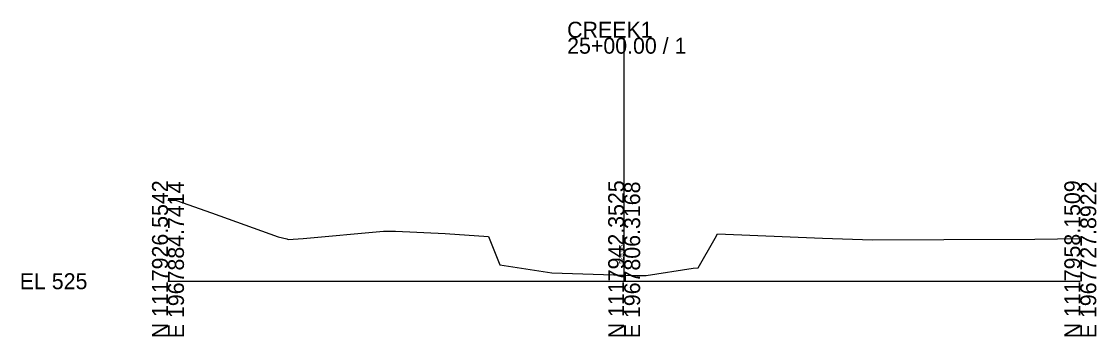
# Model space of a CAD drawing. Extents: x -26 to 163, y -10 to 10052.
# Drawn here: x -25.7 to 162.8, y 4490.3 to 4545.5 of the extents above; entities that cross this region are included whole.
import ezdxf

# ---------------------------------------------------------------- set-up
doc = ezdxf.new("R2010")
doc.units = 0
for name, color, linetype in [('RD_GPK_XS_Cell', 7, 'Continuous'), ('RD_XS_ExGround', 7, 'Continuous'), ('RD_XS_TX_Elev_EX', 7, 'Continuous')]:
    doc.layers.add(name, color=color, linetype=linetype)

msp = doc.modelspace()

# ---------------------------------------------------------------- linework, layer by layer
at = {"layer": 'RD_GPK_XS_Cell'}
for p, q in [((80, 4500), (80, 4542.7)), ((0, 4500), (80, 4500)), ((80, 4500), (160, 4500))]:
    msp.add_line(p, q, dxfattribs=at)
at = {"layer": 'RD_XS_ExGround'}
for p, q in [((0, 4514.23), (1.48, 4514.15)), ((1.48, 4514.15), (7.62, 4511.98)), ((7.62, 4511.98), (19.3, 4507.77)), ((23.68, 4507.51), (37.77, 4508.79)), ((37.77, 4508.79), (39.92, 4508.75)), ((39.92, 4508.75), (48.6, 4508.36)), ((48.6, 4508.36), (56.21, 4507.86)), ((56.21, 4507.86), (58.2, 4502.87)), ((95.96, 4507.54), (96.38, 4508.29)), ((96.38, 4508.29), (114.79, 4507.55)), ((19.3, 4507.77), (20.86, 4507.45)), ((20.86, 4507.45), (21.09, 4507.3)), ((21.09, 4507.3), (23.68, 4507.51)), ((92.99, 4502.37), (95.96, 4507.54)), ((114.79, 4507.55), (123.57, 4507.25)), ((123.57, 4507.25), (136.07, 4507.3)), ((136.07, 4507.3), (152.02, 4507.38)), ((152.02, 4507.38), (160, 4507.48)), ((58.2, 4502.87), (67.32, 4501.46)), ((83.87, 4501.02), (92.11, 4502.28)), ((92.11, 4502.28), (92.99, 4502.37)), ((67.32, 4501.46), (80, 4501.05)), ((80, 4501.05), (82.28, 4500.98)), ((82.28, 4500.98), (83.87, 4501.02))]:
    msp.add_line(p, q, dxfattribs=at)

# ---------------------------------------------------------------- texts
at = {"layer": 'RD_GPK_XS_Cell'}
for s, p in [('CREEK1', (70, 4542.7)), ('25+00.00 / 1', (70, 4539.9)), ('EL 525', (-26, 4498.6))]:
    msp.add_text(s, height=2.8, dxfattribs=at).set_placement(p)
for s, p in [('N 1117926.5542', (0, 4490)), ('E 1967884.7414', (2.8, 4490)), ('N 1117942.3525', (80, 4490)), ('E 1967806.3168', (82.8, 4490)), ('N 1117958.1509', (160, 4490)), ('E 1967727.8922', (162.8, 4490))]:
    msp.add_text(s, height=2.8, rotation=90, dxfattribs=at).set_placement(p)
at = {"layer": 'RD_XS_TX_Elev_EX'}
msp.add_text('526.05', height=0.8, rotation=90, dxfattribs=at).set_placement((79.9, 4503.05))

doc.saveas('drawing.dxf')
